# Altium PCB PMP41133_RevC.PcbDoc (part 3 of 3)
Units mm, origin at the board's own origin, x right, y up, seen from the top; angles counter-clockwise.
Board outline 150 x 82 mm, 4 copper layers (Top Layer, Int1 (GND), Int2 (PWR), Bottom Layer), stack 1.369 mm thick; 186 components, 74 nets, 388 pads, 329 vias.
Unrouted connection lines stored in the file: 2.
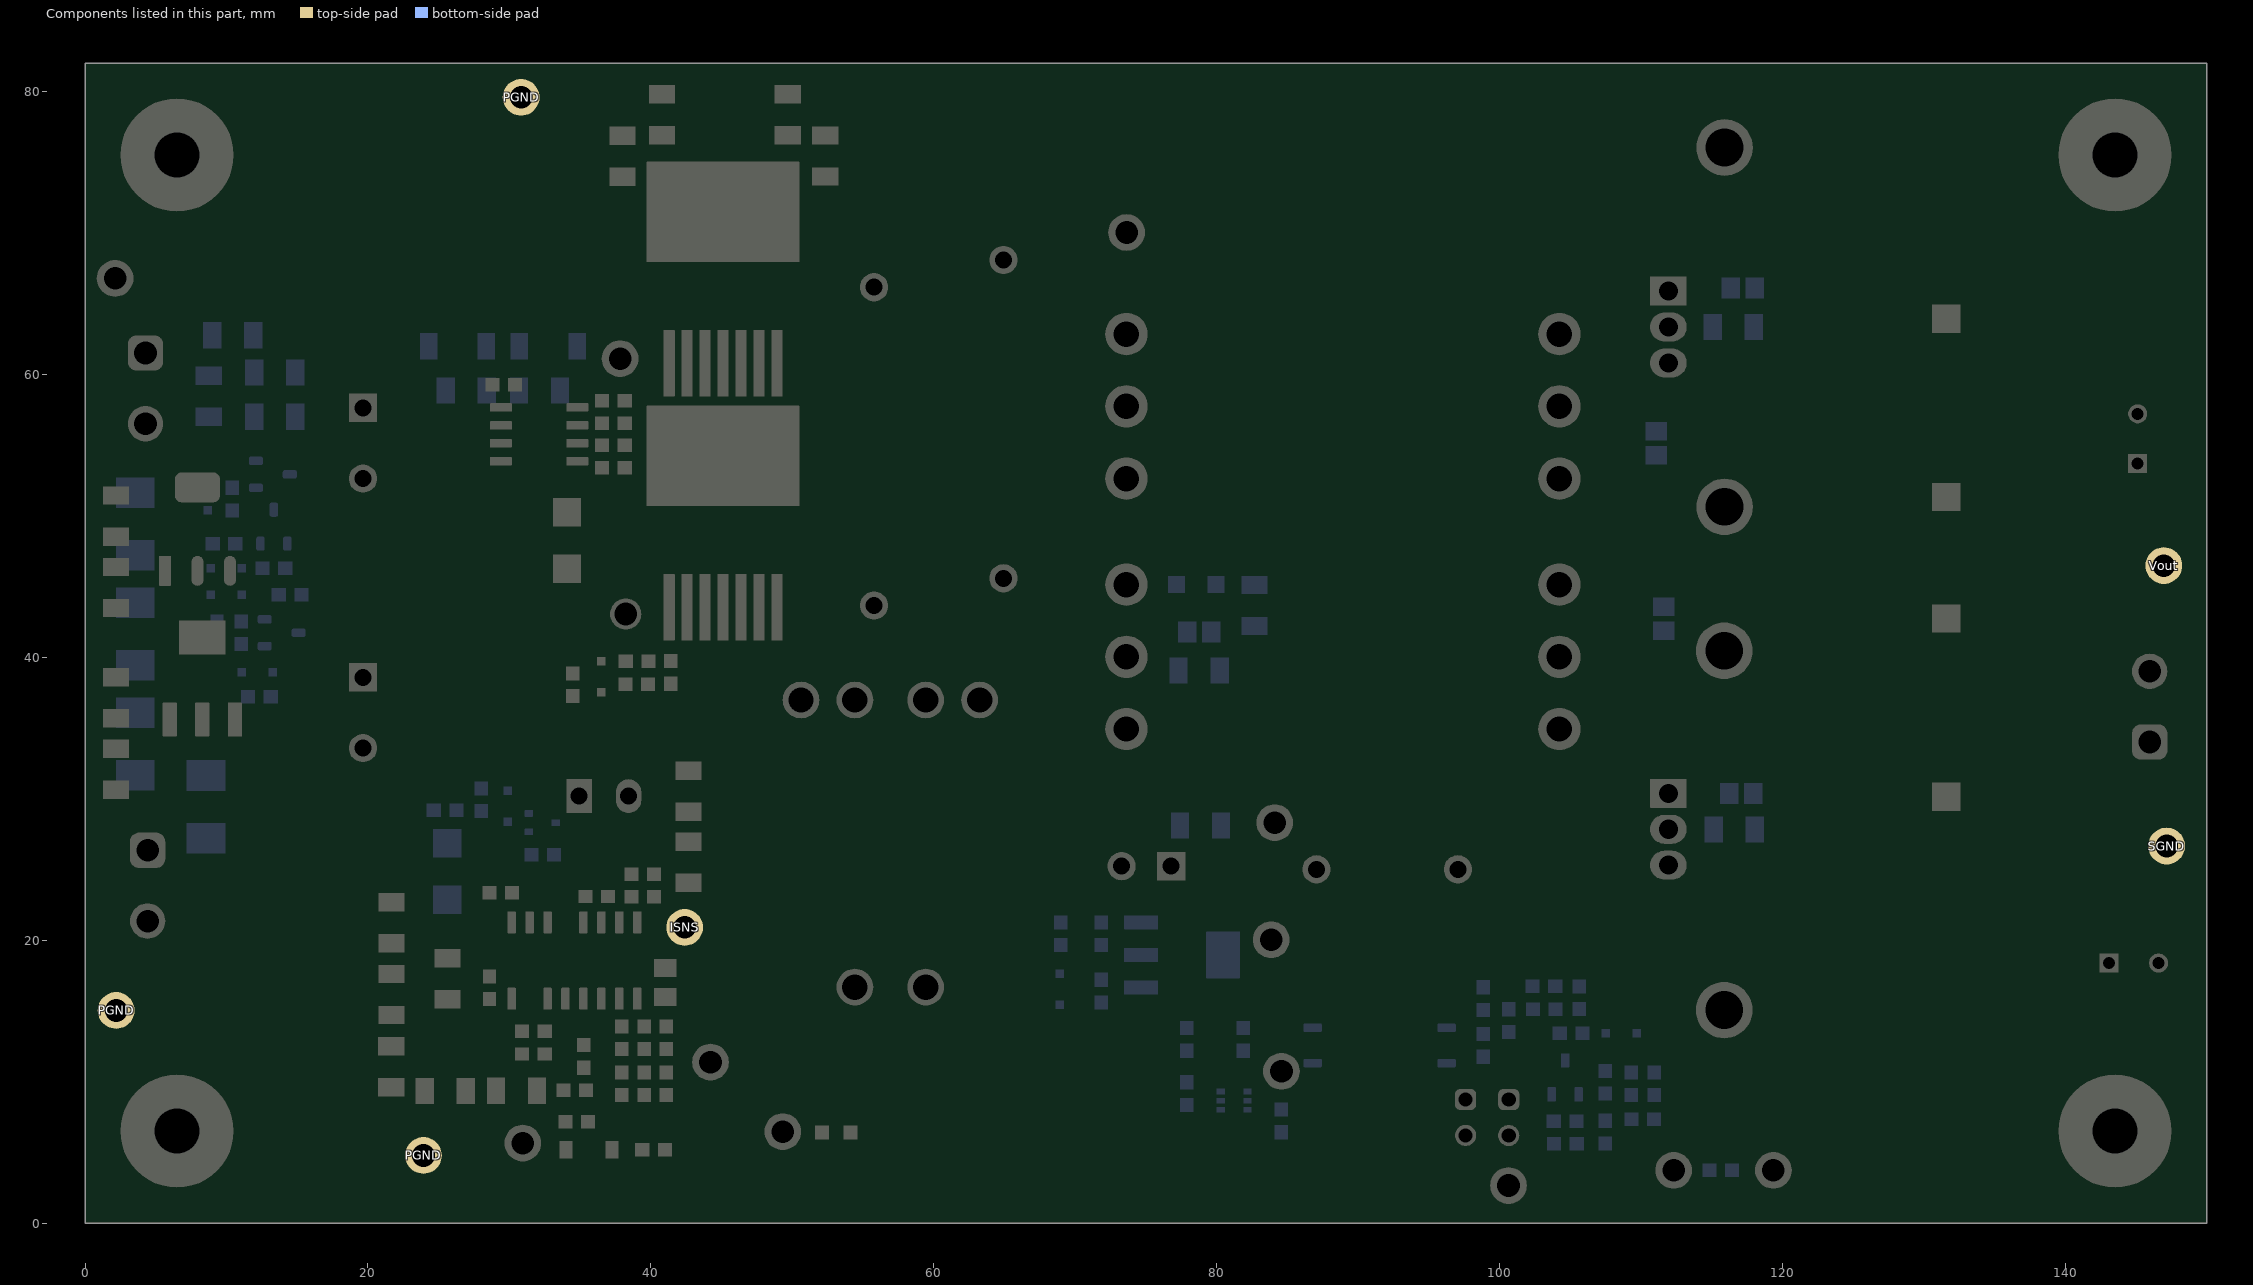
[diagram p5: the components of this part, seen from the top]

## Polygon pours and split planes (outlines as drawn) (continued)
PGND on Int2 (PWR) "INT2_(PWR)_PGND_P062" (solid, remove dead copper, pour order 62): 15.425,47.15 2.85,47.15 1.55,45.85 1.55,31.625 3.65,29.525 10.625,29.525 13.1,27.05 13.1,5.1 17.2,1 85,1 87.5,3.5 87.5,21.4 82.35,26.55 82.35,29.55 80.9,31 73.5,31 66.8,24.3 66.8,17.675 62.55,13.425 49.031,13.425 45.975,16.481 45.975,27.565 44.015,29.525 34.8,29.525 33.993,28.718 33.993,27.718 33.993,19.668 32.875,18.55 24.5,18.55 23.5,19.55 23.5,27.85 23,28.35 20.275,28.35 15.15,33.475 15.15,34.775 16.45,36.075 16.45,46.125
PGND on Int2 (PWR) "INT2_(PWR)_PGND_P060" (solid, remove dead copper, pour order 60): 1.55,28.05 8.225,28.05 9.95,26.325 9.95,14.075 8.575,12.7 1.575,12.7 0.55,13.725 0.55,27.05
HS on Int2 (PWR) "INT2_(PWR)_HS_P037" (solid, remove dead copper, pour order 37): 70.025,54.4 62.625,61.8 43.343,61.8 43.343,57.843 42.85,57.35 39.85,57.35 39.85,50.2 40.45,49.6 69.625,49.6 74.4,49.6 76.159,51.359 76.159,53.275 76.131,53.275 75.006,54.4
NetC3_2 on Int2 (PWR) "INT2_(PWR)_NETC3_2_P038" (solid, remove dead copper, pour order 38): 53.8,44.825 53.8,39.827 52.298,38.325 50.2,38.325 49.26,37.385 49.26,35.588 50.053,34.795 55.17,34.795 55.79,35.415 55.79,37.815 58.781,40.806 65.806,40.806 67.047,42.047 67.047,45.403 65.775,46.675 55.65,46.675
SGND on Int2 (PWR) "INT2_(PWR)_SGND_P032" (solid, remove dead copper, pour order 32): 136.25,81.325 105.025,81.325 101.825,78.125 101.825,21.375 103.95,19.25 109.032,19.25 114.101,14.181 114.101,8.049 115.551,6.6 131.875,6.6 141.125,15.85 141.125,19.4 142.775,21.05 147.9,21.05 149.325,22.475 149.325,69.025 148,70.35 141,70.35 138.325,73.025 138.325,79.25
SGND on Int2 (PWR) "INT2_(PWR)_SGND_P024" (solid, remove dead copper, pour order 24): 108.925,17.975 113.125,13.775 113.125,7.325 114.85,5.6 132.358,5.6 142.4,15.642 142.4,18.975 143.15,19.725 147.55,19.725 149.175,18.1 149.175,14.975 146.875,12.675 142.275,12.675 137.525,7.925 137.525,2.175 136.025,0.675 97.15,0.675 95.6,2.225 95.6,16.525 97.05,17.975
HS on Int1 (GND) "INT1_(GND)_HS_P054" (solid, remove dead copper, pour order 54): 44.05,61.825 46.375,61.825 46.95,61.25 46.95,50.475 46.125,49.65 40.625,49.65 40.025,50.25 40.025,56.7 40.425,57.1 42.8,57.1 43.625,57.925 43.625,61.4
PGND on Int1 (GND) "INT1_(GND)_PGND_P043" (solid, remove dead copper, pour order 43): 64.8,81.475 68.025,78.25 68.025,66.525 66.325,64.825 63.525,64.825 61.45,66.9 61.45,73.325 61.45,75.75 58.05,79.15 34.5,79.15 32.65,77.3 27.625,77.3 26.325,78.6 26.325,80.7 27.1,81.475
PGND on Int1 (GND) "INT1_(GND)_PGND_P049" (solid, remove dead copper, pour order 49): 43.025,44.5 43.025,37.675 40.675,35.325 40.675,25.9 41.625,24.95 44.05,24.95 44.45,24.55 44.45,14.7 45.475,13.675 60.1,13.675 66.8,20.375 66.8,24.225 72.7,30.125 86.425,30.125 87.825,28.725 87.825,2.45 85.875,0.5 16.15,0.5 14.425,2.225 14.425,12.675 20,18.25 33.275,18.25 34.625,19.6 34.625,33.475 33.375,34.725 33.375,42.7 35.4,44.725 42.8,44.725
NetL1_2 on Int1 (GND) "INT1_(GND)_NETL1_2_P047" (solid, remove dead copper, pour order 47): 75.525,59.225 61.525,59.225 59.175,56.875 59.175,41.362 58.125,40.312 58.125,35.275 58.975,34.425 63.413,34.425 64.5,35.512 64.5,40.788 61.55,43.737 61.55,48.345 69.08,55.875 75.325,55.875 76.225,56.775 76.225,58.525
PGND on Int1 (GND) "INT1_(GND)_PGND_P051" (solid, remove dead copper, pour order 51): 14.275,42.9 15.75,41.425 15.75,37 17.425,35.325 20.387,35.325 20.987,34.725 20.987,27.013 14,20.025 3.875,20.025 3.125,20.775 3.125,40.45 3.625,40.95 5.575,42.9
VIN on Int1 (GND) "INT1_(GND)_VIN_P050" (solid, remove dead copper, pour order 50): 45.075,76.675 46.8,74.95 46.8,67.925 46,67.125 31.45,67.125 24.3,59.975 24.3,57.35 22.95,56 19.025,56 17.425,57.6 17.425,70.35 21.8,74.725 34.45,74.725 36.4,76.675
PGND on Int1 (GND) "INT1_(GND)_PGND_P048" (solid, remove dead copper, pour order 48): 45.725,80.075 45.725,79.375 49.325,75.775 49.325,46.275 47.625,44.575 47.625,44.55 44.075,44.55 44.05,44.575 43.35,43.875 43.35,39.75 44.025,39.075 47.275,39.075 49.05,40.85 51.025,40.85 51.55,41.375 51.55,81.125 51.2,81.475 47.125,81.475
HS on Int1 (GND) "INT1_(GND)_HS_P016" (solid, remove dead copper, pour order 16): 43.05,61.775 43.05,58.236 42.389,57.575 39.875,57.575 39.6,57.3 39.6,52.68 36.495,49.575 34.025,49.575 33.35,50.25 33.35,60.5 35.875,63.025 41.8,63.025
SGND on Int1 (GND) "INT1_(GND)_SGND_P034" (solid, remove dead copper, pour order 34): 108.925,17.975 97.05,17.975 96.15,17.075 96.15,1.675 97.15,0.675 136.025,0.675 137.525,2.175 137.525,4.538 136.463,5.6 114.85,5.6 113.125,7.325 113.125,13.775
Vout on Int1 (GND) "INT1_(GND)_VOUT_P033" (solid, remove dead copper, pour order 33): 138.325,79.25 138.306,79.25 136.231,81.325 105.025,81.325 101.825,78.125 101.825,21.375 103.95,19.25 109.032,19.25 114.101,14.181 114.101,8.049 115.551,6.6 136.2,6.6 142.275,12.675 146.875,12.675 149.325,15.125 149.325,69.025 148,70.35 141,70.35 138.325,73.025
HS_CTRL on Int1 (GND) "INT1_(GND)_HS_CTRL_P015" (solid, remove dead copper, pour order 15): 30.347,60.975 30.9,60.422 30.9,53.15 28.975,51.225 28.975,47.925 31.868,45.032 31.868,23.257 33.05,22.075 33.05,20.125 32.407,19.482 28.902,19.482 26.75,21.634 26.75,26.45 29.8,29.5 29.8,43.125 26.5,46.425 26.5,59.24 28.235,60.975
ISNS on Top Layer "TOP_LAYER_ISNS_P078" (solid, remove dead copper, pour order 78): 39.725,25.125 43.2,25.125 43.8,24.525 43.8,20.15 43.225,19.575 41.8,19.575 40.9,20.475 38.8,20.475 38.8,22.025 39.375,22.025 39.725,22.375
PGND on Top Layer "TOP_LAYER_PGND_P077" (solid, remove dead copper, pour order 77): 37.475,12.8 40,12.8 40,10.15 37.475,10.15
PGND on Top Layer "TOP_LAYER_PGND_P076" (solid, remove dead copper, pour order 76): 37.475,21.4 37.475,20.225 36.775,19.525 36.15,19.525 35.55,20.125 34.75,20.125 32.825,18.2 28.4,18.2 28.1,17.9 28.1,16.9 39.8,16.9 40.3,17.4 41.8,17.4 41.8,18.65 40.375,20.075 38.525,20.075 38.05,20.55 38.05,21.4
VIN on Top Layer "TOP_LAYER_VIN_P074" (solid, remove dead copper, pour order 74): 22.275,74.625 18.35,70.7 18.35,59.1 17.9,58.65 17.375,58.65 17.05,58.975 17.05,64.65 12.6,69.1 1.525,69.1 0.475,68.05 0.475,51.575 1.275,50.775 9.15,50.775 9.55,51.175 9.55,56.275 10.25,56.975 12.7,56.975 13.65,56.025 18.975,56.025 20.551,56.001 21.221,56.671 21.221,57.946 21.75,58.475 22.85,58.475 31.5,67.125 50.05,67.125 52.375,64.8 56.8,64.8 57.95,65.95 57.95,69.975 53.3,74.625
HS on Top Layer "TOP_LAYER_HS_P057" (solid, remove dead copper, pour order 57): 70.163,54.4 62.762,61.8 43.481,61.8 43.481,57.843 42.988,57.35 39.988,57.35 39.988,50.2 40.588,49.6 69.762,49.6 74.537,49.6 76.296,51.359 76.296,53.275 76.269,53.275 75.144,54.4
NetC3_2 on Top Layer "TOP_LAYER_NETC3_2_P056" (solid, remove dead copper, pour order 56): 54.423,45.448 54.423,40.45 52.298,38.325 50.2,38.325 49.26,37.385 49.26,34.795 47.09,32.625 42.45,32.625 42.467,32.608 42.467,31.325 53.587,31.325 56.55,34.288 56.55,38.575 58.781,40.806 65.806,40.806 67.047,42.047 67.047,45.403 65.775,46.675 55.65,46.675
PGND on Top Layer "TOP_LAYER_PGND_P053" (solid, remove dead copper, pour order 53): 64.8,81.475 68.025,78.25 68.025,66.525 66.325,64.825 63.525,64.825 61.45,66.9 61.45,73.325 61.45,75.75 58.05,79.15 34.5,79.15 32.65,77.3 27.625,77.3 26.325,78.6 26.325,80.7 27.1,81.475
NetL1_2 on Top Layer "TOP_LAYER_NETL1_2_P039" (solid, remove dead copper, pour order 39): 59.025,38.825 63.6,38.825 64.525,37.9 64.525,35.725 63.525,34.725 59.125,34.725 58.125,35.725 58.125,37.925
PGND on Top Layer "TOP_LAYER_PGND_P036" (solid, remove dead copper, pour order 36): 43.343,44.568 51.488,44.568 52.001,44.055 52.001,41.376 51.4,40.775 49.037,40.775 47.296,39.034 43.977,39.034 43.343,39.668
SGND on Top Layer "TOP_LAYER_SGND_P030" (solid, remove dead copper, pour order 30): 136.231,81.325 138.175,79.381 138.175,73.275 141.05,70.4 147.156,70.4 148.728,68.828 148.728,56.538 147.64,55.45 111.025,55.45 109.9,56.575 109.9,60.875 110.85,61.825 113,61.825 113.75,62.575 113.75,64.225 113.125,64.85 110.1,64.85 108.575,66.375 108.575,79.4 110.5,81.325
VD1 on Top Layer "TOP_LAYER_VD1_P027" (solid, remove dead copper, pour order 27): 102.95,41.85 107.775,41.85 108.85,40.775 108.85,29.55 109.55,28.85 112.6,28.85 113.225,28.225 113.225,27.35 112.675,26.8 102.85,26.8 101.75,27.9 101.75,40.7 102.925,41.875
Vout on Top Layer "TOP_LAYER_VOUT_P026" (solid, remove dead copper, pour order 26): 101.725,53.524 103.126,54.925 147.975,54.925 149.35,53.55 149.35,38.7 147.752,37.102 114.725,37.102 109.137,42.69 103.56,42.69 101.725,44.525
SGND on Top Layer "TOP_LAYER_SGND_P025" (solid, remove dead copper, pour order 25): 149.425,29.675 149.425,13.85 148.025,12.45 140.25,12.45 138.675,14.025 138.675,26.425 141.925,29.675
VD2 on Top Layer "TOP_LAYER_VD2_P023" (solid, remove dead copper, pour order 23): 112.765,64.375 103.018,64.375 101.705,63.062 101.705,56.553 102.873,55.385 108.047,55.385 109.3,56.638 109.3,61 110.625,62.325 112.75,62.325 113.25,62.825 113.25,63.89
SGND on Top Layer "TOP_LAYER_SGND_P022" (solid, remove dead copper, pour order 22): 114.175,36.175 147.45,36.175 149.425,34.2 149.425,23.6 148.075,22.25 138.675,22.25 133.975,26.95 131.85,26.95 131.85,25.425 135.625,21.65 135.625,12.2 132.2,8.775 110.175,8.775 103.475,15.475 103.475,25.2 104.6,26.325 113.05,26.325 113.85,27.125 113.85,28.625 113.1,29.375 110.6,29.375 109.8,30.175 109.8,35.125 110.85,36.175
PGND on Bottom Layer "BOTTOM_LAYER_PGND_P083" (solid, remove dead copper, pour order 83): 26.625,33.525 26.725,33.425 42.989,33.425 45.545,30.869 45.545,24.745 44.025,23.225 41.95,23.225 39.95,21.225 38.15,21.225 38.15,21.239 37.45,21.939 37.45,25.43 37.941,25.921 37.941,28.084 35.85,30.175 31.9,30.175 25.825,30.175 25.025,30.975 25.025,31.775 26.65,33.4 26.65,33.525
PGND on Bottom Layer "BOTTOM_LAYER_PGND_P082" (solid, remove dead copper, pour order 82): 26.15,61.689 24.914,62.925 23.6,62.925 23.6,50.45 22.775,49.625 22.775,37.275 21.275,35.775 17.821,35.775 16.675,34.629 16.675,33.275 17.75,32.2 23.962,32.2 25.912,34.15 43.118,34.15 45.15,36.182 45.15,37.85 45.975,38.675 47.15,38.675 49.05,40.575 50.148,40.575 51.05,41.477 51.05,45.4 50,46.45 28.95,46.45 26.15,49.25
VIN on Bottom Layer "BOTTOM_LAYER_VIN_P069" (solid, remove dead copper, pour order 69): 58.025,76.6 59.4,75.225 59.4,66.325 58.075,65 48.875,65 47.725,66.15 21.7,66.15 18.925,63.375 15.15,63.375 11.5,67.025 11.5,68.822 17.703,75.025 33.625,75.025 35.2,76.6
VIN on Bottom Layer "BOTTOM_LAYER_VIN_P079" (solid, remove dead copper, pour order 79): 20.925,56.575 20.425,56.075 14.2,56.075 14.2,64.95 13.213,65.937 6.962,65.937 5.775,64.75 5.775,55.35 5.1,54.675 1.425,54.675 0.575,55.525 0.575,67.825 1.8,69.05 19.85,69.05 20.925,67.975
NetL1_2 on Bottom Layer "BOTTOM_LAYER_NETL1_2_P052" (solid, remove dead copper, pour order 52): 75.525,59.225 65.662,59.225 59.175,52.738 59.175,39.55 58.125,38.5 58.125,35.275 58.975,34.425 63.413,34.425 64.5,35.512 64.5,40.788 61.55,43.737 61.55,48.345 69.08,55.875 75.325,55.875 76.225,56.775 76.225,58.525
PGND on Bottom Layer "BOTTOM_LAYER_PGND_P075" (solid, remove dead copper, pour order 75): 28.75,80.9 28.75,79.025 30,77.775 32.7,77.775 34.05,79.125 59.5,79.125 62.175,76.45 62.175,67.775 63.3,66.65 67.475,66.65 68.45,67.625 68.45,77.475 64.45,81.475 29.325,81.475
PGND on Bottom Layer "BOTTOM_LAYER_PGND_P071" (solid, remove dead copper, pour order 71): 62.15,69.4 62.15,65.475 58.9,62.225 53.2,62.225 50.1,59.125 50.1,50.1 45.562,45.562 45.562,42.888 47.875,40.575 51.625,40.575 52.35,41.3 52.35,45.4 56.75,49.8 56.75,53.9 65.075,62.225 67.225,62.225 68.45,63.45 68.45,69.65 66.675,71.425 64.175,71.425
HS on Bottom Layer "BOTTOM_LAYER_HS_P067" (solid, remove dead copper, pour order 67): 47.454,61.116 45.495,63.075 36.625,63.075 35.975,62.425 35.975,58.385 34.89,57.3 33.535,57.3 32.925,56.69 32.925,50.35 33.7,49.575 46.151,49.575 47.454,50.878
PGND on Bottom Layer "BOTTOM_LAYER_PGND_P063" (solid, remove dead copper, pour order 63): 9.9,28.3 2,28.3 0.6,26.9 0.6,13.725 1.625,12.7 8.5,12.7 9.9,14.1
PGND on Bottom Layer "BOTTOM_LAYER_PGND_P042" (solid, remove dead copper, pour order 42): 78.575,38.625 77.336,37.386 72.864,37.386 72.075,38.175 72.075,41.375 72.545,41.845 76.145,41.845 76.825,42.525 78.575,42.525
NetD2_2 on Bottom Layer "BOTTOM_LAYER_NETD2_2_P041" (solid, remove dead copper, pour order 41): 77.75,46.5 76.825,47.425 72.9,47.425 72.075,46.6 72.075,43.638 72.763,42.95 75,42.95 76.575,44.525 77.75,44.525
HS_CTRL on Bottom Layer "BOTTOM_LAYER_HS_CTRL_P044" (solid, remove dead copper, pour order 44): 31.325,62.925 27.725,62.925 27.725,57.925 31.325,57.925
SGND on Bottom Layer "BOTTOM_LAYER_SGND_P031" (solid, remove dead copper, pour order 31): 136.231,81.325 138.175,79.381 138.175,73.275 141.05,70.4 147.156,70.4 148.728,68.828 148.728,56.538 147.515,55.325 110.325,55.325 109.9,55.75 109.9,60.875 110.85,61.825 118.825,61.825 119.175,62.175 119.175,66.975 118.775,67.375 117.4,67.375 116.975,66.95 116.975,65.35 116.475,64.85 110.1,64.85 108.575,66.375 108.575,79.4 110.5,81.325
VD1 on Bottom Layer "BOTTOM_LAYER_VD1_P020" (solid, remove dead copper, pour order 20): 102.95,41.85 107.775,41.85 108.85,40.775 108.85,29.55 109.55,28.85 112.6,28.85 113.25,28.2 113.25,27.375 112.675,26.8 102.85,26.8 101.75,27.9 101.75,40.7 102.925,41.875
SGND on Bottom Layer "BOTTOM_LAYER_SGND_P029" (solid, remove dead copper, pour order 29): 145.05,36.225 148.225,36.225 149,35.45 149,12.2 148.05,11.25 145.6,11.25 144.6,12.25 144.6,35.775
SGND on Bottom Layer "BOTTOM_LAYER_SGND_P028" (solid, remove dead copper, pour order 28): 110.55,42.55 116.6,42.55 122.925,36.225 141.125,36.225 141.95,35.4 141.95,14.8 132.75,5.6 114.95,5.6 113.175,7.375 113.175,13 111.375,14.8 108.1,14.8 107.05,15.85 107.05,17.6 106.55,18.1 104.3,18.1 103.396,19.004 103.396,25.096 104.625,26.325 114.631,26.325 118.725,26.325 119,26.6 119,31.225 118.65,31.575 117.175,31.575 116.875,31.275 116.875,29.625 116.6,29.35 110.575,29.35 109.75,30.175 109.75,41.75
Vout on Bottom Layer "BOTTOM_LAYER_VOUT_P017" (solid, remove dead copper, pour order 17): 101.725,53.524 103.126,54.925 147.975,54.925 149.35,53.55 149.35,38.7 147.752,37.102 122.898,37.102 117.075,42.925 103.325,42.925 101.725,44.525
VD2 on Bottom Layer "BOTTOM_LAYER_VD2_P019" (solid, remove dead copper, pour order 19): 112.765,64.375 103.018,64.375 101.705,63.062 101.705,56.553 102.873,55.385 108.047,55.385 109.3,56.638 109.3,61 110.625,62.325 112.75,62.325 113.25,62.825 113.25,63.89

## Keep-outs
Keep-Out Layer:
  text ".Layer_Name" at 14.656,-21.806 h1.52

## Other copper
Top Layer:
  text ".Layer_Name" at 14.656,-21.806 h1.52
Int1 (GND):
  pour cut-out: 85.55,25 ccw(c87.05,25) 87.05,23.5 ccw(c87.05,25) 88.55,25 ccw(c87.05,25) 87.05,26.5 ccw(c87.05,25)
Int2 (PWR):
  pour cut-out: 42.56,58.727 cw(c42.56,59.327) 41.96,59.327 cw(c42.56,59.327) 42.56,59.927 cw(c42.56,59.327) 43.16,59.327 cw(c42.56,59.327)
  pour cut-out: 38.2,51.6 cw(c38.2,52.2) 37.6,52.2 cw(c38.2,52.2) 38.2,52.8 cw(c38.2,52.2) 38.8,52.2 cw(c38.2,52.2)
  pour cut-out: 34.9,58.05 ccw(c34.9,58.65) 35.5,58.65 ccw(c34.9,58.65) 34.9,59.25 ccw(c34.9,58.65) 34.3,58.65 ccw(c34.9,58.65)
Bottom Layer:
  pour cut-out: 38.2,51.6 cw(c38.2,52.2) 37.6,52.2 cw(c38.2,52.2) 38.2,52.8 cw(c38.2,52.2) 38.8,52.2 cw(c38.2,52.2)
  pour cut-out: 42.56,58.727 cw(c42.56,59.327) 41.96,59.327 cw(c42.56,59.327) 42.56,59.927 cw(c42.56,59.327) 43.16,59.327 cw(c42.56,59.327)
  text ".Layer_Name" at 14.656,-21.806 h1.52

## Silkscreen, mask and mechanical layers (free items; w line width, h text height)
Top Overlay:
  lines w0.2: 25.375,25.95 32.175,25.95 34.125,24 34.125,22.525 34.575,22.075 40.55,22.075
  text "PMP41133" at 81.375,76.525 h2.75
  text "Vin" at 9.075,58.275 h1.5
  text "PGND" at 9.275,19.675 h1.5
  text ".Layer_Name" at 14.656,-21.806 h1.52
Bottom Overlay:
  text ".Layer_Name" at 14.656,-21.806 h1.52
Top Paste:
  text ".Layer_Name" at 14.656,-21.806 h1.52
Bottom Paste:
  text ".Layer_Name" at 14.656,-21.806 h1.52
Top Solder:
  text ".Layer_Name" at 14.656,-21.806 h1.52
  text ".Layer_Name" at 14.656,-21.806 h1.52
Bottom Solder:
  text ".Layer_Name" at 14.656,-21.806 h1.52
Drill Guide:
  text ".Layer_Name" at 14.656,-21.806 h1.52
M1 Board Outline:
  the board outline again, w0.254
  text ".Layer_Name" at 14.656,-21.806 h1.52
M2 Board Dimensions:
  rectangle: 0,-6.985 3.175,-3.81
  rectangle: 3.175,-10.16 12.7,-6.985
  lines w0.178: 0,-6.985 25.4,-6.985 ; 3.175,-10.16 3.175,-3.81 ; 6.35,-10.16 6.35,-3.81 ; 12.7,-10.16 12.7,-3.81 ; 19.05,-10.16 19.05,-3.81 ; 0,-10.16 25.4,-10.16 25.4,-3.81 0,-3.81 0,-10.16
  text ".Layer_Name" at 14.656,-21.806 h1.52
M3 3D STEP Top:
  text ".Layer_Name" at 14.656,-21.806 h1.52
M4 3D STEP Bottom:
  text ".Layer_Name" at 14.656,-21.806 h1.52
M5 Assembly Top:
  lines w0.254: -7.417,-23.626 160.223,-23.626 ; -7.417,-18.462 160.274,-18.462 ; -7.417,-13.297 -7.417,-28.791 94.31,-28.791 160.274,-28.791 160.274,-13.297 -7.404,-13.297 -7.404,-28.791 32.614,-28.791 ; 55.194,-28.791 55.194,-13.297 ; 87.376,-18.462 87.376,-13.297 ; 108.712,-18.462 108.712,-13.297 ; 124.511,-28.956 124.511,-23.804
  text "COMPONENTS MARKED 'DNP' SHOULD NOT BE POPULATED." at 29.299,-8.09 h1.52
  text "ASSEMBLY VARIANT:" at 29.286,-11.024 h1.52
  text ".VariantName" at 55.601,-11.024 h1.52
  text "PCB VIEWED FROM TOP SIDE" at -5.804,-16.654 h1.52
  text "BOARD #:" at 57.099,-16.654 h1.52
  text ".PRJ_Number" at 70.955,-16.654 h1.52
  text "REV:" at 92.405,-16.654 h1.52
  text ".PCB_Rev" at 99.809,-16.654 h1.52
  text "SVN REV:" at 113.69,-16.654 h1.52
  text ".VersionControl_RevNumber" at 126.543,-16.654 h1.52
  text "TID #:" at 57.099,-21.819 h1.52
  text ".TID" at 70.955,-21.819 h1.52
  text "PLOT NAME =" at -5.804,-27.034 h1.52
  text ".plot_File_Name" at 14.656,-27.034 h1.52
  text "GENERATED    :" at 57.15,-27.034 h1.52
  text ".Print_Date" at 79.235,-27.034 h1.52
  text ".Print_Time" at 97.752,-27.034 h1.52
  text "TEXAS INSTRUMENTS" at 129.87,-27.034 h1.52
M6 Assembly Bottom:
  lines w0.254: -7.429,-18.474 160.261,-18.474 ; -7.379,-23.639 160.261,-23.639 ; 28.334,-28.969 28.334,-23.817 ; 44.133,-18.474 44.133,-13.31 ; 65.468,-18.474 65.468,-13.31 ; 97.65,-28.804 97.65,-13.31 ; 120.231,-28.804 160.249,-28.804 160.249,-13.31 -7.429,-13.31 -7.429,-28.804 58.534,-28.804 160.261,-28.804 160.261,-13.31
  text "COMPONENTS MARKED 'DNP' SHOULD NOT BE POPULATED." at 154.991,-8.077 h1.52
  text ".VariantName" at 128.473,-11.024 h1.52
  text "ASSEMBLY VARIANT:" at 154.864,-11.024 h1.52
  text ".VersionControl_RevNumber" at 26.302,-16.667 h1.52
  text "SVN REV:" at 39.154,-16.667 h1.52
  text ".PCB_Rev" at 53.035,-16.667 h1.52
  text "REV:" at 60.439,-16.667 h1.52
  text ".PRJ_Number" at 81.89,-16.667 h1.52
  text "BOARD #:" at 95.745,-16.667 h1.52
  text "PCB VIEWED FROM BOTTOM SIDE" at 158.648,-16.667 h1.52
  text ".TID" at 81.89,-21.831 h1.52
  text "TID #:" at 95.745,-21.831 h1.52
  text "TEXAS INSTRUMENTS" at 22.974,-27.047 h1.52
  text ".Print_Time" at 55.093,-27.047 h1.52
  text ".Print_Date" at 73.609,-27.047 h1.52
  text "GENERATED    :" at 95.694,-27.047 h1.52
  text ".plot_File_Name" at 138.189,-27.047 h1.52
  text "PLOT NAME =" at 158.648,-27.047 h1.52
M9 Title Sheet:
  drawing of 57 lines, arcs and shapes, not listed
  text "1" at 18.792,204.127 h1.78
  text "2" at 82.182,204.127 h1.78
  text "3" at 145.411,204.127 h1.78
  text "4" at 209.08,204.127 h1.78
  text "5" at 272.555,204.127 h1.78
  text "6" at 336.182,204.127 h1.78
  text "A" at -10.579,175.095 h1.78
  text "A" at 365.341,175.095 h1.78
  text "B" at -10.579,114.643 h1.78
  text "B" at 365.341,114.643 h1.78
  text "C" at -10.579,54.318 h1.78
  text "C" at 365.341,54.318 h1.78
  text "PROJECT TITLE:" at 288.125,7.048 h1.14
  text ".PRJ_Title" at 289.395,3.662 h1.78
  text "DESIGNED FOR:" at 288.125,-0.597 h1.14
  text ".PRJ_Customer" at 289.395,-4.153 h1.78
  text "D" at -10.579,-5.88 h1.78
  text "D" at 365.341,-5.88 h1.78
  text "FILE NAME:" at 288.125,-8.217 h1.14
  text ".PCB_File_Name_No_Path" at 289.395,-11.265 h1.78
  text "Texas Instruments (TI) and/or its licensors do not warrant the accuracy or completeness of this specification" at 161.9,-15.376 h1.14
  text "ENGINEER:" at 288.125,-15.583 h1.14
  text "LAYOUT BY:" at 326.352,-15.583 h1.14
  text "or any information contained therein. TI and/or its licensors do not warrant that this design will meet" at 160.757,-18.237 h1.14
  text ".PRJ_Engineer" at 289.395,-19.52 h1.78
  text ".PCB_Layout" at 327.635,-19.52 h1.78
  text "the specifications, will be suitable for your application or fit for any particular purpose, or will operate in" at 160.757,-21.099 h1.14
  text ".Layer_Name" at 14.656,-21.806 h1.52
  text "ALTIUM DESIGNER VERSION:" at 326.352,-23.457 h1.14
  text "an implementation. TI and/or its licensors do not warrant that the design is production worthy. You should" at 160.757,-23.961 h1.14
  text "completely validate and test your design implementation to confirm the system functionality for your application." at 161.9,-26.822 h1.14
  text ".print_Scale" at 289.395,-26.843 h1.78
  text ".Application_BuildNumber" at 327.635,-26.843 h1.78
  text "1" at 18.792,-32.093 h1.78
  text "2" at 82.182,-32.093 h1.78
  text "3" at 145.411,-32.093 h1.78
  text "4" at 209.08,-32.093 h1.78
  text "5" at 272.555,-32.093 h1.78
  text "6" at 336.182,-32.093 h1.78
M10 Fab Notes:
  drawing of 189 lines, arcs and shapes, not listed
  text "DESIGN INFORMATION" at 314.503,161.447 h1.52
  text "MIN. TRACK WIDTH:" at 298.131,158.091 h1.52
  text "8" at 325.976,158.091 h1.52
  text "MIL" at 329.907,158.091 h1.52
  text "7.874" at 321.75,155 h1.52
  text "MIN. CLEARANCE:" at 298.131,154.938 h1.52
  text "MIL" at 329.907,154.938 h1.52
  text "MIN. VIA PAD SIZE:" at 298.131,151.785 h1.52
  text "24" at 325.214,151.785 h1.52
  text "MIL" at 329.907,151.785 h1.52
  text "0.05mm (2MIL)" at 315.784,148.486 h1.52
  text "MINIMUM ANNULAR RING" at 289.769,148.277 h1.52
  text "EXTERNAL" at 333.768,148.277 h1.52
  text "PER" at 294.849,145.48 h1.52
  text "IPC-D-275 CLASS 2 LEVEL C" at 300.437,145.48 h1.52
  text "MIL, HOLES" at 338.238,142.928 h1.52
  text "+/-" at 328.27,142.709 h1.52
  text "+/-" at 349.961,142.709 h1.52
  text "REGISTRATION TOLERANCES:" at 289.769,142.682 h1.52
  text "METAL" at 320.243,142.682 h1.52
  text "5" at 334.879,142.683 h1.52
  text "3" at 356.037,142.683 h1.52
  text "MIL" at 358.99,142.682 h1.52
  text "HOLE SIZE TOLERANCE (UNLESS OTHERWISE SPECIFIED):" at 289.769,140.185 h1.52
  text "+/-" at 349.961,140.112 h1.52
  text "3" at 356.037,140.085 h1.52
  text "MIL" at 358.99,140.085 h1.52
  text "MATERIAL:" at 287.87,136.589 h1.52
  text "FR-4 High Tg" at 312.926,133.324 h1.52
  text "X" at 309.257,133.122 h1.52
  text "FR-4" at 298.563,133.007 h1.52
  text "OTHER" at 336.358,133.007 h1.52
  text "62 MIL (1.6mm) +/-10%" at 306.694,129.374 h1.52
  text "X" at 303.643,129.312 h1.52
  text "THICKNESS:" at 289.769,129.165 h1.52
  text "OTHER" at 339.33,129.165 h1.52
  text "TOLERANCE:" at 289.769,125.652 h1.52
  text "X" at 311.314,125.652 h1.52
  text "ANSI IPC-6012 TYPE 3 CLASS 2" at 315.836,125.652 h1.52
  text "OTHER +/-" at 315.835,121.989 h1.52
  text "BOW & TWIST:" at 289.769,118.302 h1.52
  text "X" at 311.314,118.302 h1.52
  text "ANSI IPC-6012 TYPE 3 CLASS 2" at 315.836,118.302 h1.52
  text "OTHER +/-" at 315.835,114.576 h1.52
  text "DRILLING:" at 287.87,111.258 h1.52
  text "NC_DRILL FILES" at 332.599,108.586 h1.52
  text "REFERENCE:" at 289.769,108.486 h1.52
  text "X" at 306.463,108.484 h1.52
  text "AS SHOWN" at 310.984,108.486 h1.52
  text "X" at 329.348,108.486 h1.52
  text "OTHER" at 340.168,104.873 h1.52
  text "PTH COPPER THICKNESS:" at 289.761,104.783 h1.52
  text "X" at 318.697,104.783 h1.52
  text "20-30 um" at 321.948,104.783 h1.52
  text "BOARD FINISH:" at 287.87,101.034 h1.52
  text "SILKSCREEN:" at 291.812,98.237 h1.52
  text "X" at 316.14,98.237 h1.52
  text "TOP" at 319.112,98.237 h1.52
  text "X" at 329.094,98.237 h1.52
  text "BOTTOM" at 332.091,98.237 h1.52
  text "SILKSCREEN COLOR:" at 291.812,94.295 h1.52
  text "X" at 316.115,94.295 h1.52
  text "WHITE" at 319.112,94.295 h1.52
  text "OTHER" at 332.091,94.295 h1.52
  text "X" at 319.442,90.652 h1.52
  text "GREEN" at 322.439,90.652 h1.52
  text "OTHER" at 338.136,90.652 h1.52
  text "SOLDER RESIST COLOR:" at 291.812,90.477 h1.52
  text "X" at 319.442,86.734 h1.52
  text "MATTE" at 322.439,86.734 h1.52
  text "SEMI-GLOSS" at 338.125,86.717 h1.52
  text "IMMERSION GOLD (ENIG)" at 314.819,82.345 h1.52
  text "ENEPIG" at 348.793,82.162 h1.52
  text "SURFACE FINISH:" at 287.87,82.136 h1.52
  text "IMM. TIN/SILVER OR EQUIV" at 296.24,78.649 h1.52
  text "OTHER" at 332.599,78.549 h1.52
  text "X" at 292.25,78.5 h1.52
  text "ARRAY/PANEL:" at 287.87,74.602 h1.52
  text "CUT AND TRIM PER M1 BOARD OUTLINE" at 314.819,74.393 h1.52
  text "N.C. ROUTE" at 314.819,70.94 h1.52
  text "X" at 332.295,70.94 h1.52
  text "V. SCORE" at 336.816,70.94 h1.52
  text "CERTIFICATION:" at 287.87,67.66 h1.52
  text "MATERIALS AND WORKMANSHIP FOR ALL PCBS" at 306.285,67.66 h1.52
  text "TO MEET OR EXCEED THE REQUIREMENTS OF:" at 306.285,65.271 h1.52
  text "X" at 297.078,62.003 h1.52
  text "ANSI IPC-A-600F CLASS ->" at 300.329,62.003 h1.52
  text "X" at 342.188,62.003 h1.52
  text "2" at 344.982,62.003 h1.52
  text "1" at 336.981,61.965 h1.52
  text "3" at 353.973,61.965 h1.52
  text "X" at 317.702,58.252 h1.52
  text "RoHS" at 320.953,58.252 h1.52
  text "OTHER" at 337.321,58.252 h1.52
  text "PER ORDER" at 347.407,58.252 h1.52
  text "ALL BOARDS MUST MEET OR EXCEED UL94-V0 REQUIREMENTS." at 288.569,54.345 h1.52
  text "PCB MUST BEAR THE UL94V-0 UL REGISTERED MATERIAL ID NUMBER" at 288.569,51.397 h1.52
  text "ADDITIONAL REQUIREMENTS:" at 287.87,47.094 h1.52
  text "MICROSECTION:" at 289.769,44.373 h1.52
  text "YES" at 312.775,44.373 h1.52
  text "REQUIRED" at 334.657,40.707 h1.52
  text "BARE BOARD ELEC. TEST:" at 289.769,40.634 h1.52
  text "NONE" at 322.935,40.634 h1.52
  text "X" at 331.66,40.634 h1.52
  text "PER ORDER" at 349.693,40.634 h1.52
  text "XX MIL VIAS REQUIRE NON-CONDUCTIVE FILL AND PLANARIZE" at 294.04,35.428 h1.5
  text "XX MIL VIAS REQUIRE CONDUCTIVE FILL AND PLANARIZE" at 294.243,32.787 h1.52
  text "OUTER XX MIL TRACES REQUIRE 50 OHM SINGLE-ENDED IMPEDANCE" at 294.218,28.637 h1.47
  text "LAYER 2 & 3 (INNER LAYERS) XX MIL WIDE, XX MIL SPACE / TRACES REQUIRE 100 OHM DIFFERENTIAL IMPEDANCE" at 294.015,22.65 h1.52
  text ".Layer_Name" at 14.656,-21.806 h1.52
M11 Gerber Information:
  lines w0.254: -7.417,-23.626 160.223,-23.626 ; -7.417,-18.462 160.274,-18.462 ; -7.417,-13.297 -7.417,-28.791 94.31,-28.791 160.274,-28.791 160.274,-13.297 -7.404,-13.297 -7.404,-28.791 32.614,-28.791 ; 55.194,-28.791 55.194,-13.297 ; 87.376,-18.462 87.376,-13.297 ; 108.712,-18.462 108.712,-13.297 ; 124.511,-28.956 124.511,-23.804
  text "ALL ARTWORK VIEWED FROM TOP SIDE" at -5.804,-16.654 h1.52
  text "BOARD #:" at 57.099,-16.654 h1.52
  text ".PRJ_Number" at 70.955,-16.654 h1.52
  text "REV:" at 92.405,-16.654 h1.52
  text ".PCB_Rev" at 99.809,-16.654 h1.52
  text "SVN REV:" at 113.69,-16.654 h1.52
  text ".VersionControl_RevNumber" at 126.543,-16.654 h1.52
  text "LAYER NAME =" at -5.804,-21.806 h1.52
  text "TID #:" at 57.099,-21.819 h1.52
  text ".TID" at 70.955,-21.819 h1.52
  text "PLOT NAME =" at -5.804,-27.034 h1.52
  text ".plot_File_Name" at 14.656,-27.034 h1.52
  text "GENERATED    :" at 57.15,-27.034 h1.52
  text ".Print_Date" at 79.235,-27.034 h1.52
  text ".Print_Time" at 97.752,-27.034 h1.52
  text "TEXAS INSTRUMENTS" at 129.87,-27.034 h1.52
M12 Stackup:
  drawing of 399 lines, arcs and shapes, not listed
  text "Layer" at 169.462,199.636 h1.52
  text "Name" at 179.873,199.636 h1.52
  text "Material" at 213.646,199.636 h1.52
  text "Thickness" at 228.882,199.636 h1.52
  text "Constant" at 245.388,199.636 h1.52
  text "Board Layer Stack" at 259.862,199.636 h1.52
  text "Top Overlay" at 179.873,196.588 h1.52
  text "Top Solder" at 179.873,193.54 h1.52
  text "SM-001" at 213.646,193.54 h1.52
  text "1.00mil" at 228.882,193.54 h1.52
  text "4" at 245.388,193.54 h1.52
  text "Top Surface Finish" at 179.873,190.492 h1.52
  text "PbSn" at 213.646,190.492 h1.52
  text "0.79mil" at 228.882,190.492 h1.52
  text "1" at 169.462,187.444 h1.52
  text "Top Layer" at 179.873,187.444 h1.52
  text "CF-004" at 213.646,187.444 h1.52
  text "1.38mil" at 228.882,187.444 h1.52
  text "Dielectric 1" at 179.873,184.396 h1.52
  text "PP-017" at 213.646,184.396 h1.52
  text "5.10mil" at 228.882,184.396 h1.52
  text "4.3" at 245.388,184.396 h1.52
  text "Dielectric 2" at 179.873,181.348 h1.52
  text "PP-017" at 213.646,181.348 h1.52
  text "5.10mil" at 228.882,181.348 h1.52
  text "4.3" at 245.388,181.348 h1.52
  text "2" at 169.462,178.3 h1.52
  text "Int1 (GND)" at 179.873,178.3 h1.52
  text "CF-004" at 213.646,178.3 h1.52
  text "1.38mil" at 228.882,178.3 h1.52
  text "Dielectric 3" at 179.873,175.252 h1.52
  text "Core-039" at 213.646,175.252 h1.52
  text "28.00mil" at 228.882,175.252 h1.52
  text "4.8" at 245.388,175.252 h1.52
  text "3" at 169.462,172.204 h1.52
  text "Int2 (PWR)" at 179.873,172.204 h1.52
  text "CF-004" at 213.646,172.204 h1.52
  text "1.38mil" at 228.882,172.204 h1.52
  text "Dielectric 4" at 179.873,169.156 h1.52
  text "PP-017" at 213.646,169.156 h1.52
  text "5.10mil" at 228.882,169.156 h1.52
  text "4.3" at 245.388,169.156 h1.52
  text "Dielectric 5" at 179.873,166.108 h1.52
  text "PP-017" at 213.646,166.108 h1.52
  text "5.10mil" at 228.882,166.108 h1.52
  text "4.3" at 245.388,166.108 h1.52
  text "4" at 169.462,163.06 h1.52
  text "Bottom Layer" at 179.873,163.06 h1.52
  text "CF-004" at 213.646,163.06 h1.52
  text "1.38mil" at 228.882,163.06 h1.52
  text "Bottom Surface Finish" at 179.873,160.012 h1.52
  text "PbSn" at 213.646,160.012 h1.52
  text "0.79mil" at 228.882,160.012 h1.52
  text "Bottom Solder" at 179.873,156.964 h1.52
  text "SM-001" at 213.646,156.964 h1.52
  text "1.00mil" at 228.882,156.964 h1.52
  text "4" at 245.388,156.964 h1.52
  text "Bottom Overlay" at 179.873,153.916 h1.52
  text ".Layer_Name" at 14.656,-21.806 h1.52
M13 Component Bodies Top:
  text ".Layer_Name" at 14.656,-21.806 h1.52
M14 Component Bodies Bottom:
  text ".Layer_Name" at 14.656,-21.806 h1.52
M15 Courtyards Top:
  lines w1.14: 10.294,52.599 10.211,52.682 10.211,55.865 10.55,56.204 11.672,56.204 13.575,54.301 13.575,48.875 ; 23.65,18.825 32.588,18.825 33.67,19.907 33.67,23.219 ; 32.45,36.55 32.45,46.575
  lines w2.28: 19.05,10.251 19.05,20.276 ; 19.314,23.831 22.076,26.593 22.076,38.756 ; 21.945,44.246 21.945,54.271 ; 25.624,49.661 25.624,59.422 30.529,64.327 45.399,64.327 48.076,67.005 48.076,75.205 ; 47.985,38.087 49.507,39.609 51.987,39.609 53.185,40.806 53.185,46.11 55.411,48.336 75.306,48.336 ; 48.051,49.605 48.051,57.805
  lines w8: 92.025,0.032 92.025,33.545
  text ".Layer_Name" at 14.656,-21.806 h1.52
M16 Courtyards Bottom:
  lines w1.14: 6.622,36.671 6.622,50.473 ; 8.701,35.549 14.231,30.019 ; 17.256,39.193 17.256,52.996 ; 18.139,36.501 20.883,36.501 21.625,37.243 21.625,45.7
  lines w1.5: 7.025,54.036 7.025,59.625 ; 10.475,54.836 10.475,60.425
  lines w2.28: 22.338,50.741 22.338,63.431 23.264,64.358 ; 32.569,48.213 46.53,48.213 48.863,50.545 48.863,59.906 52.747,63.789 58.644,63.789 60.846,65.992 60.846,69.281 ; 47.014,77.828 52.911,77.828 ; 52.635,40.518 52.635,45.552 54.436,47.352 56.003,47.352 ; 56.949,34.435 56.949,38.083 ; 57.996,40.057 57.996,53.311 64.963,60.277 ; 64.202,47.857 64.082,47.857 62.7,46.475 62.7,44.411 63.785,43.326 67.433,43.326
  text ".Layer_Name" at 14.656,-21.806 h1.52
Drill Drawing:
  circle w0.254: c82.449,192.722 r0.703
  lines w0.254: 81.746,166.721 83.152,166.721 83.152,168.127 81.746,168.127 81.746,166.721 ; 81.746,169.883 83.152,169.883 83.152,171.289 81.746,171.289 81.746,169.883 ; 81.746,177.613 83.152,177.613 82.449,176.208 81.746,177.613 ; 81.746,180.776 83.152,180.776 82.449,179.37 81.746,180.776 ; 81.746,182.884 82.097,182.884 82.097,182.533 82.8,182.533 82.8,182.884 83.152,182.884 83.152,183.587 82.8,183.587 82.8,183.938 82.097,183.938 82.097,183.587 81.746,183.587 81.746,182.884 ; 81.746,186.046 82.097,186.046 82.449,185.695 82.8,186.046 83.152,186.046 82.8,186.398 83.152,186.749 82.8,186.749 82.449,187.1 82.097,186.749 81.746,186.749 82.097,186.398 81.746,186.046 ; 81.746,188.857 81.746,189.209 82.097,189.56 81.746,189.911 81.746,190.263 82.097,190.263 82.449,189.911 82.8,190.263 83.152,190.263 83.152,189.911 82.8,189.56 83.152,189.209 83.152,188.857 82.8,188.857 82.449,189.209 82.097,188.857 81.746,188.857 ; 81.746,195.182 82.449,195.533 83.152,195.182 82.8,195.885 83.152,196.587 82.449,196.236 81.746,196.587 82.097,195.885 81.746,195.182 ; 82.027,167.002 82.87,167.002 82.87,167.845 82.027,167.845 82.027,167.002 ; 82.027,180.495 82.87,180.495 82.449,179.651 82.027,180.495 ; 82.027,183.024 82.238,183.024 82.238,182.814 82.66,182.814 82.66,183.024 82.87,183.024 82.87,183.446 82.66,183.446 82.66,183.657 82.238,183.657 82.238,183.446 82.027,183.446 82.027,183.024 ; 82.027,189.138 82.027,189.349 82.238,189.56 82.027,189.771 82.027,189.982 82.238,189.982 82.449,189.771 82.66,189.982 82.87,189.982 82.87,189.771 82.66,189.56 82.87,189.349 82.87,189.138 82.66,189.138 82.449,189.349 82.238,189.138 82.027,189.138 ; 82.027,195.463 82.449,195.674 82.87,195.463 82.66,195.885 82.87,196.306 82.449,196.095 82.027,196.306 82.238,195.885 82.027,195.463
  lines w0.305: 80.472,165.772 162.57,165.772 ; 80.472,197.395 162.57,197.395 ; 89.058,162.61 89.058,200.558 ; 97.494,162.61 97.494,200.558 ; 113.661,162.61 113.661,200.558 ; 120.245,162.61 120.245,200.558 ; 129.776,162.61 129.776,200.558 ; 148.179,162.61 148.179,200.558 ; 80.472,162.61 162.57,162.61 162.57,200.558 80.472,200.558 80.472,162.61
  text "Symbol" at 82.369,198.344 h1.83
  text "Quantity" at 90.006,198.344 h1.83
  text "Finished Hole Size" at 98.443,198.344 h1.83
  text "Plated" at 114.61,198.344 h1.83
  text "Hole Type" at 121.193,198.344 h1.83
  text "Drill Layer Pair" at 130.724,198.344 h1.83
  text "Hole Tolerance" at 149.128,198.344 h1.83
  text "329" at 90.006,195.182 h1.52
  text "11.81mil (0.300mm)" at 98.443,195.182 h1.52
  text "PTH" at 114.61,195.182 h1.52
  text "Round" at 121.193,195.182 h1.52
  text "Top Layer - Bottom Layer" at 130.724,195.182 h1.52
  text "4" at 90.006,192.019 h1.52
  text "33.47mil (0.850mm)" at 98.443,192.019 h1.52
  text "PTH" at 114.61,192.019 h1.52
  text "Round" at 121.193,192.019 h1.52
  text "Top Layer - Bottom Layer" at 130.724,192.019 h1.52
  text "4" at 90.006,188.857 h1.52
  text "39.37mil (1.000mm)" at 98.443,188.857 h1.52
  text "PTH" at 114.61,188.857 h1.52
  text "Round" at 121.193,188.857 h1.52
  text "Top Layer - Bottom Layer" at 130.724,188.857 h1.52
  text "+3.94mil/-1.97mil" at 149.128,188.857 h1.52
  text "14" at 90.006,185.695 h1.52
  text "47.24mil (1.200mm)" at 98.443,185.695 h1.52
  text "PTH" at 114.61,185.695 h1.52
  text "Round" at 121.193,185.695 h1.52
  text "Top Layer - Bottom Layer" at 130.724,185.695 h1.52
  text "6" at 90.006,182.533 h1.52
  text "53.15mil (1.350mm)" at 98.443,182.533 h1.52
  text "PTH" at 114.61,182.533 h1.52
  text "Round" at 121.193,182.533 h1.52
  text "Top Layer - Bottom Layer" at 130.724,182.533 h1.52
  text "24" at 90.006,179.37 h1.52
  text "62.99mil (1.600mm)" at 98.443,179.37 h1.52
  text "PTH" at 114.61,179.37 h1.52
  text "Round" at 121.193,179.37 h1.52
  text "Top Layer - Bottom Layer" at 130.724,179.37 h1.52
  text "1" at 90.006,176.208 h1.52
  text "63.00mil (1.600mm)" at 98.443,176.208 h1.52
  text "PTH" at 114.61,176.208 h1.52
  text "Round" at 121.193,176.208 h1.52
  text "Top Layer - Bottom Layer" at 130.724,176.208 h1.52
  text "18" at 90.006,173.046 h1.52
  text "70.87mil (1.800mm)" at 98.443,173.046 h1.52
  text "PTH" at 114.61,173.046 h1.52
  text "Round" at 121.193,173.046 h1.52
  text "Top Layer - Bottom Layer" at 130.724,173.046 h1.52
  text "A" at 81.727,172.792 h1.41
  text "4" at 90.006,169.883 h1.52
  text "105.12mil (2.670mm)" at 98.443,169.883 h1.52
  text "PTH" at 114.61,169.883 h1.52
  text "Round" at 121.193,169.883 h1.52
  text "Top Layer - Bottom Layer" at 130.724,169.883 h1.52
  text "4" at 90.006,166.721 h1.52
  text "125.98mil (3.200mm)" at 98.443,166.721 h1.52
  text "PTH" at 114.61,166.721 h1.52
  text "Round" at 121.193,166.721 h1.52
  text "Top Layer - Bottom Layer" at 130.724,166.721 h1.52
  text "408 Total" at 90.006,163.559 h1.52
  text ".Layer_Name" at 14.656,-21.806 h1.52
M17 Embedded Cavity:
  text ".Layer_Name" at 14.656,-21.806 h1.52
M18 Embedded Assembly:
  text ".Layer_Name" at 14.656,-21.806 h1.52
M19 Embedded Keepout:
  text ".Layer_Name" at 14.656,-21.806 h1.52

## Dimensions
0,82 to 0,0 on M2 Board Dimensions
0,82 to 150,82 on M2 Board Dimensions
0,-10.16 to 25.4,-10.16 on M2 Board Dimensions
